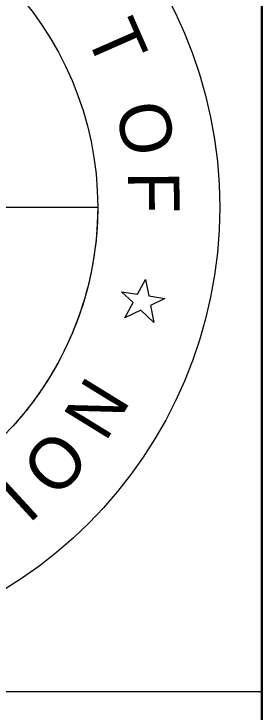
# Model space of a CAD drawing. Extents: x 0 to 1.42, y 0 to 0.92.
# Drawn here: x 1.382 to 1.39587, y 0.16135 to 0.20039 of the extents above; entities that cross this region are included whole.
import ezdxf

# ---------------------------------------------------------------- set-up
doc = ezdxf.new("R2010")
doc.units = 0
for name, color, linetype in [('P_ODOT_PLAN_Border', 7, 'Continuous'), ('P_ODOT_PLAN_General', 7, 'Continuous'), ('P_ODOT_PLAN_TBlock', 7, 'Continuous')]:
    doc.layers.add(name, color=color, linetype=linetype)

msp = doc.modelspace()

# ---------------------------------------------------------------- linework, layer by layer
at = {"layer": 'P_ODOT_PLAN_Border'}
msp.add_lwpolyline([(0.06250000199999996, 0.041666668), (1.395833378, 0.041666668), (1.395833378, 0.8750000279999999), (0.06250000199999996, 0.8750000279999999)], close=True, dxfattribs=at)
at = {"layer": 'P_ODOT_PLAN_General'}
msp.add_lwpolyline([(1.395866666, 0.041666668), (0.8890384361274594, 0.041666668), (0.8890384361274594, 0.22282299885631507), (1.395866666, 0.22282299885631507)], close=True, dxfattribs=at)
at = {"layer": 'P_ODOT_PLAN_TBlock'}
msp.add_line((1.1208776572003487, 0.16250000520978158), (1.395866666, 0.16250000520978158), dxfattribs=at)
for points in [[(0.9583666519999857, 0.041666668), (1.395866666, 0.041666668), (1.395866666, 0.2166666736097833), (0.9583666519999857, 0.2166666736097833)], [(1.3880103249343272, 0.1848549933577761), (1.3889103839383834, 0.1847124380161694), (1.3893595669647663, 0.18553218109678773), (1.3895334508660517, 0.18461375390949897), (1.3904335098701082, 0.1844711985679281), (1.3896331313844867, 0.1840872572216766), (1.389813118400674, 0.18313659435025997), (1.3890894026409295, 0.18382643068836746), (1.3881879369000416, 0.18339399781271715), (1.3886528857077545, 0.1842425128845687)]]:
    msp.add_lwpolyline(points, close=True, dxfattribs=at)
msp.add_lwpolyline([(1.3804766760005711, 0.18958333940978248), (1.3866780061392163, 0.18958333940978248), (1.3866780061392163, 0.18952169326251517), (1.3866780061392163, 0.18940716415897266), (1.3866673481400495, 0.18896253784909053), (1.386659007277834, 0.18875289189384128), (1.3866261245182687, 0.18818244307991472), (1.3865722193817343, 0.18760269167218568), (1.3865644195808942, 0.18749200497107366), (1.3864842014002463, 0.18693729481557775), (1.3864775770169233, 0.1868913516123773), (1.3864776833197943, 0.18689099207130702), (1.3864770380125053, 0.186886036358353), (1.3864662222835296, 0.18681656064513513), (1.3864546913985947, 0.18674307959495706), (1.3864306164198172, 0.18659549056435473), (1.3864129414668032, 0.18649127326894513), (1.3863836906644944, 0.18632581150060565), (1.3863527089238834, 0.186160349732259), (1.3863117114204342, 0.1859530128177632), (1.3862630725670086, 0.18572221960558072), (1.3862115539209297, 0.18549142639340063), (1.3861370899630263, 0.18518173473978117), (1.3860895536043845, 0.18499577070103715), (1.3860213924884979, 0.18474192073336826), (1.3859549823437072, 0.1845091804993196), (1.3859125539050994, 0.18436399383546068), (1.3859123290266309, 0.18436322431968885), (1.3859100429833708, 0.18435540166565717), (1.385902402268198, 0.18433005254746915), (1.3858375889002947, 0.18412007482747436), (1.3857356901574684, 0.18380654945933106), (1.3856152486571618, 0.18345896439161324), (1.3854846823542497, 0.18310794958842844), (1.385388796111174, 0.18285955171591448), (1.3853309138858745, 0.1827159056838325), (1.385321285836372, 0.18269231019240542), (1.3853137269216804, 0.18267388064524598), (1.385307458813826, 0.18265864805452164), (1.385303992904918, 0.18265036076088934), (1.3853035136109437, 0.18264921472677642), (1.3853007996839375, 0.1826425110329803), (1.385288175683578, 0.18261203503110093), (1.385261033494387, 0.18254764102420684), (1.385127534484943, 0.18223715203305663), (1.3850548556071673, 0.18207476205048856), (1.385013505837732, 0.18198733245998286), (1.3849900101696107, 0.18193368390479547), (1.3849006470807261, 0.18174395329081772), (1.384782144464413, 0.18150057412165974), (1.3846185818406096, 0.18117913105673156), (1.3844689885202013, 0.1808980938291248), (1.384383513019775, 0.1807426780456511), (1.3843549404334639, 0.18069152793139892), (1.3842133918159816, 0.18044371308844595), (1.38415949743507, 0.18035165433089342), (1.384099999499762, 0.18025147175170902), (1.3840207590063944, 0.1801202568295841), (1.3839483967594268, 0.18000263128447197), (1.3838671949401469, 0.17987285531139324), (1.3838321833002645, 0.1798176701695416), (1.3838136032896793, 0.17978855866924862), (1.3838021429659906, 0.17977066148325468), (1.3837008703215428, 0.1796144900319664), (1.3834648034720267, 0.17926349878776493), (1.3834349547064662, 0.17922032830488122), (1.383365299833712, 0.17911925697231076), (1.3831621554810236, 0.17883641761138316), (1.383102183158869, 0.17875644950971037), (1.3830872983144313, 0.1787364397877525), (1.3829566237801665, 0.17856040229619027), (1.3826702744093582, 0.17819488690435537), (1.3826085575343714, 0.17812058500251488), (1.3825394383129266, 0.17803603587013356), (1.3824521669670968, 0.17793074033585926), (1.3823750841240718, 0.1778389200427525), (1.3821988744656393, 0.17763397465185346), (1.382149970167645, 0.17757819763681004), (1.382055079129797, 0.1774710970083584), (1.3820236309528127, 0.17743546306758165), (1.3818720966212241, 0.1772688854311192)], dxfattribs=at)
for radius in [0.025000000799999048, 0.018178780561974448]:
    msp.add_circle((1.3684992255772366, 0.18958333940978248), radius, dxfattribs=at)

# ---------------------------------------------------------------- texts
for s, height, rotation, p in [('T', 0.0028694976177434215, 293.7296823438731, (1.385970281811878, 0.1992657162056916)), ('O', 0.0028694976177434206, 281.0153190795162, (1.3876728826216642, 0.195183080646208)), ('F', 0.0028694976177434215, 270.4549130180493, (1.3883743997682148, 0.19157423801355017)), ('N', 0.0028694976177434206, 58.37169331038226, (1.3871042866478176, 0.1763908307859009)), ('O', 0.0028694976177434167, 47.81128724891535, (1.3843713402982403, 0.17320449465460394)), ('I', 0.0028694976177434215, 42.57913222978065, (1.3828115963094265, 0.17182533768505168))]:
    msp.add_text(s, height=height, rotation=rotation, dxfattribs=at).set_placement(p)

doc.saveas('drawing.dxf')
